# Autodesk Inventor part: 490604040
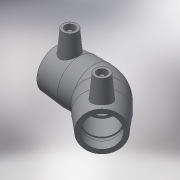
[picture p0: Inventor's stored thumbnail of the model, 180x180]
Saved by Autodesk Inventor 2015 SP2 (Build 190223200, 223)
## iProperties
Created: 2017-06
Part Number: 490604040
Material: Generic
Description: PLASSON 45° ELBOW 40
Document SubType Name: Modeling
Designer: KIM
Mass: 55.0731 g
Surface Area: 148.067 cm^2
Volume: 55.0731 cm^3
Density: 1 g/cm^3
Appearance: Default
Author: KIM
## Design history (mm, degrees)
derived "490604.ipt"
feature "Solid1::490604.ipt"
tag "TaggingFeature1"
body "Solid1"
other parameters: "d2" = 55, "d4" = 27, "d5" = 49.5, "d8" = 168 deg, "d10" = 16.8, "d11" = 5.6, "d14" = 17.6296, "d19" = 3.52592, "d20" = 168 deg, "d22" = 50.6, "d23" = 55, "d24" = 49.082, "d29" = 46, "d30" = 15, "d31" = 37.8, "d34" = 5 deg, "d35" = 12, "d39" = 0, "d41" = 4, "d42" = 14, "d43" = 0, "d44" = 9.6, "d45" = 4.8, "d46" = 6, "d47" = 0, "d50" = 34, "d51" = 16.8, "d52" = 42, "d54" = 135 deg, "d67" = 45 deg, "d71" = 135 deg, "d75" = 2.75, "d82" = 45 deg, "d83" = 42, "d84" = 49.5, "d86" = 24.75, "d87" = 135 deg, "d88" = 108, "d90" = 42, "d91" = 0, "d92" = 42, "d93" = 0, "d94" = 135 deg, "d95" = 25.3, "d98" = 108, "d99" = 32.4, "d101" = 3, "d102" = 0, "d103" = 3, "d104" = 0, "d105" = 12.18, "d106" = 3.045, "L_" = 108, "L_1" = 42, "D_" = 55, "A_" = 46, "d_2" = 12
